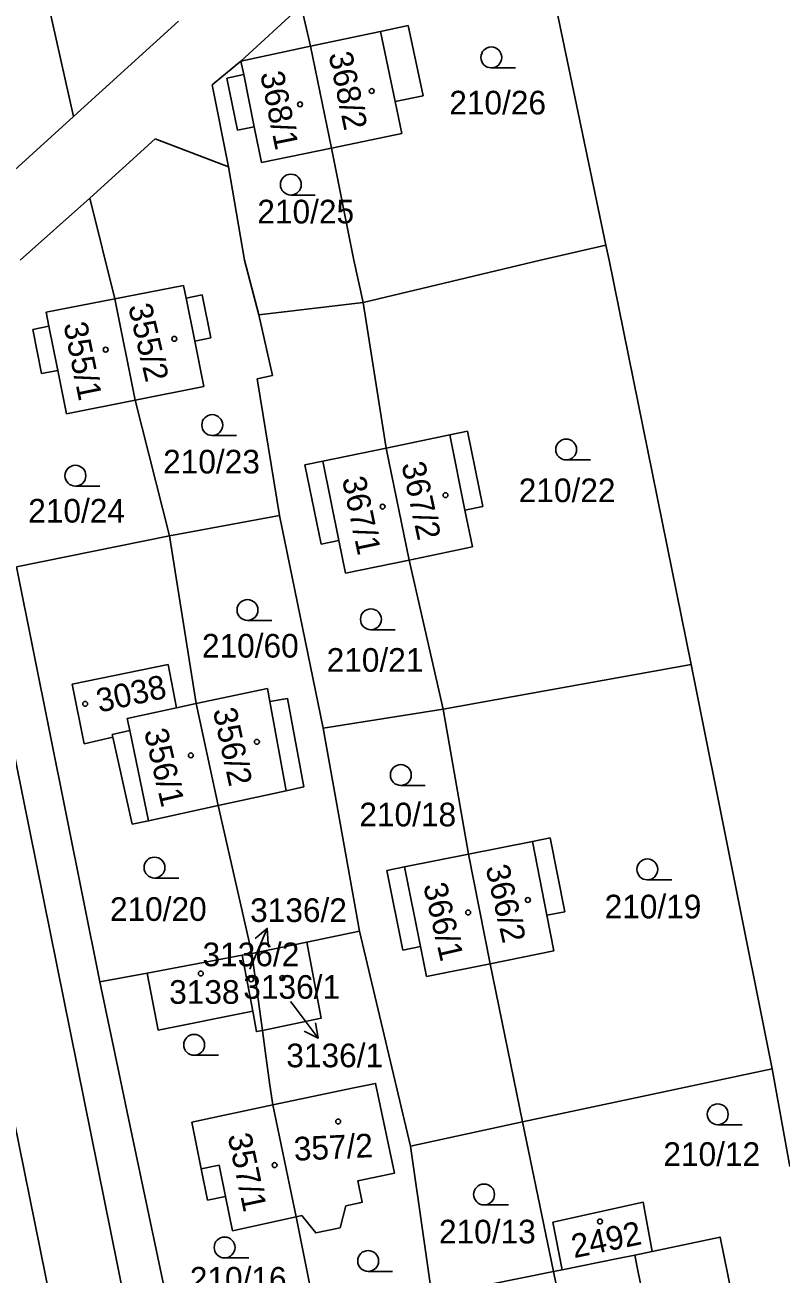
# Model space of a CAD drawing. Extents: x -735249 to -729401, y -1124843 to -1121828.
# Drawn here: x -733298.6 to -733244.3, y -1123572.8 to -1123483.1 of the extents above; entities that cross this region are included whole.
import ezdxf

# ---------------------------------------------------------------- set-up
doc = ezdxf.new("R2010")
doc.units = 0
for name, color, linetype in [('Vrstva 1', 7, 'Continuous'), ('Vrstva 16', 7, 'Continuous'), ('Vrstva 18', 7, 'Continuous'), ('Vrstva 19', 7, 'Continuous'), ('Vrstva 25', 7, 'Continuous'), ('Vrstva 4', 7, 'Continuous')]:
    doc.layers.add(name, color=color, linetype=linetype)

msp = doc.modelspace()

# ---------------------------------------------------------------- linework, layer by layer
at = {"layer": 'Vrstva 1'}
for points in [[(-733256.9, -1123498.91), (-733261.01, -1123479.3)], [(-733297.03, -1123481.32), (-733295.16, -1123489.66)], [(-733278.81, -1123481.71), (-733283.13, -1123485.69)], [(-733278.81, -1123481.71), (-733278.12, -1123484.62)], [(-733295.16, -1123489.66), (-733287.62, -1123482.81)], [(-733273.11, -1123483.55), (-733278.12, -1123484.62)], [(-733273.11, -1123483.55), (-733271.11, -1123483.12)], [(-733270.04, -1123488.18), (-733271.11, -1123483.12)], [(-733278.12, -1123484.62), (-733276.61, -1123491.94)], [(-733283.13, -1123485.69), (-733285.19, -1123487.38)], [(-733283.13, -1123485.69), (-733282.93, -1123486.66)], [(-733285.19, -1123487.38), (-733284.01, -1123493.28)], [(-733284.14, -1123486.91), (-733282.93, -1123486.66)], [(-733283.38, -1123490.65), (-733284.14, -1123486.91)], [(-733272.05, -1123488.6), (-733270.04, -1123488.18)], [(-733271.56, -1123490.9), (-733272.05, -1123488.6)], [(-733303.9, -1123497.59), (-733295.16, -1123489.66)], [(-733282.17, -1123490.41), (-733283.38, -1123490.65)], [(-733281.65, -1123492.98), (-733282.17, -1123490.41)], [(-733271.56, -1123490.9), (-733276.61, -1123491.94)], [(-733289.29, -1123491.28), (-733293.99, -1123495.53)], [(-733284.01, -1123493.28), (-733289.29, -1123491.28)], [(-733281.65, -1123492.98), (-733276.61, -1123491.94)], [(-733275.01, -1123500), (-733276.61, -1123491.94)], [(-733284.01, -1123493.28), (-733282.87, -1123500)], [(-733293.99, -1123495.53), (-733298.99, -1123500)], [(-733293.99, -1123495.53), (-733292.19, -1123502.77)], [(-733261.61, -1123500), (-733256.9, -1123498.91)], [(-733256.68, -1123500), (-733256.9, -1123498.91)], [(-733311.97, -1123500), (-733277.47, -1123670.28)], [(-733277.33, -1123644.79), (-733306.61, -1123500)], [(-733282.87, -1123500), (-733281.83, -1123503.91)], [(-733274.35, -1123503.04), (-733275.01, -1123500)], [(-733274.35, -1123503.04), (-733261.61, -1123500)], [(-733250.77, -1123529.05), (-733256.68, -1123500)], [(-733292.19, -1123502.77), (-733287.25, -1123501.81)], [(-733287.25, -1123501.81), (-733287.07, -1123502.72)], [(-733285.91, -1123502.49), (-733287.07, -1123502.72)], [(-733285.3, -1123505.58), (-733285.91, -1123502.49)], [(-733292.19, -1123502.77), (-733297.12, -1123503.72)], [(-733290.73, -1123510.06), (-733292.19, -1123502.77)], [(-733281.83, -1123503.91), (-733274.35, -1123503.04)], [(-733272.7, -1123513.5), (-733274.35, -1123503.04)], [(-733297.12, -1123503.72), (-733296.92, -1123504.74)], [(-733281.83, -1123503.91), (-733280.85, -1123508.27)], [(-733296.92, -1123504.74), (-733298.08, -1123504.97)], [(-733298.08, -1123504.97), (-733297.45, -1123508.14)], [(-733286.45, -1123505.81), (-733285.3, -1123505.58)], [(-733285.8, -1123509.08), (-733286.45, -1123505.81)], [(-733297.45, -1123508.14), (-733296.28, -1123507.91)], [(-733296.28, -1123507.91), (-733295.66, -1123511.04)], [(-733280.85, -1123508.27), (-733281.97, -1123508.51)], [(-733281.97, -1123508.51), (-733280.35, -1123518.33)], [(-733285.8, -1123509.08), (-733290.73, -1123510.06)], [(-733295.66, -1123511.04), (-733290.73, -1123510.06)], [(-733290.73, -1123510.06), (-733288.27, -1123519.79)], [(-733268.11, -1123512.55), (-733272.7, -1123513.5)], [(-733266.85, -1123512.29), (-733268.11, -1123512.55)], [(-733265.75, -1123517.7), (-733266.85, -1123512.29)], [(-733277.24, -1123514.43), (-733272.7, -1123513.5)], [(-733272.7, -1123513.5), (-733271.05, -1123521.54)], [(-733278.54, -1123514.7), (-733277.24, -1123514.43)], [(-733278.54, -1123514.7), (-733277.36, -1123520.4)], [(-733267.03, -1123517.96), (-733265.75, -1123517.7)], [(-733266.49, -1123520.6), (-733267.03, -1123517.96)], [(-733288.27, -1123519.79), (-733280.35, -1123518.33)], [(-733280.35, -1123518.33), (-733277.22, -1123533.61)], [(-733299.25, -1123522.02), (-733288.27, -1123519.79)], [(-733286.34, -1123531.86), (-733288.27, -1123519.79)], [(-733277.36, -1123520.4), (-733276.09, -1123520.13)], [(-733276.09, -1123520.13), (-733275.61, -1123522.48)], [(-733271.05, -1123521.54), (-733266.49, -1123520.6)], [(-733275.61, -1123522.48), (-733271.05, -1123521.54)], [(-733271.05, -1123521.54), (-733268.59, -1123532.26)], [(-733299.25, -1123522.02), (-733293.27, -1123551.85)], [(-733288.35, -1123529.05), (-733295.26, -1123530.46)], [(-733288.35, -1123529.05), (-733287.76, -1123532.16)], [(-733268.59, -1123532.26), (-733250.77, -1123529.05)], [(-733244.97, -1123558.11), (-733250.77, -1123529.05)], [(-733295.26, -1123530.46), (-733294.4, -1123534.74)], [(-733281.23, -1123530.77), (-733286.34, -1123531.86)], [(-733281.23, -1123530.77), (-733281.05, -1123531.71)], [(-733291.31, -1123532.92), (-733287.76, -1123532.16)], [(-733286.34, -1123531.86), (-733287.76, -1123532.16)], [(-733284.76, -1123539.18), (-733286.34, -1123531.86)], [(-733279.78, -1123531.48), (-733281.05, -1123531.71)], [(-733278.6, -1123537.84), (-733279.78, -1123531.48)], [(-733277.22, -1123533.61), (-733268.59, -1123532.26)], [(-733268.59, -1123532.26), (-733266.78, -1123542.68)], [(-733291.31, -1123532.92), (-733291.11, -1123533.8)], [(-733292.38, -1123534.08), (-733291.11, -1123533.8)], [(-733292.38, -1123534.08), (-733292.34, -1123534.28)], [(-733274.6, -1123548.2), (-733277.22, -1123533.61)], [(-733292.34, -1123534.28), (-733294.4, -1123534.74)], [(-733290.94, -1123540.53), (-733292.34, -1123534.28)], [(-733284.76, -1123539.18), (-733279.87, -1123538.12)], [(-733278.6, -1123537.84), (-733279.87, -1123538.12)], [(-733289.76, -1123540.27), (-733284.76, -1123539.18)], [(-733284.76, -1123539.18), (-733282.34, -1123549.81)], [(-733290.94, -1123540.53), (-733289.76, -1123540.27)], [(-733266.78, -1123542.68), (-733262.18, -1123541.77)], [(-733260.9, -1123541.51), (-733262.18, -1123541.77)], [(-733260.9, -1123541.51), (-733259.86, -1123546.81)], [(-733271.37, -1123543.59), (-733266.78, -1123542.68)], [(-733266.78, -1123542.68), (-733265.22, -1123550.55)], [(-733272.65, -1123543.85), (-733271.37, -1123543.59)], [(-733272.65, -1123543.85), (-733271.5, -1123549.57)], [(-733259.86, -1123546.81), (-733261.14, -1123547.06)], [(-733260.64, -1123549.63), (-733261.14, -1123547.06)], [(-733274.6, -1123548.2), (-733278.4, -1123548.99)], [(-733274.6, -1123548.2), (-733270.95, -1123563.66)], [(-733278.4, -1123548.99), (-733282.34, -1123549.81)], [(-733278.4, -1123548.99), (-733277.37, -1123554.47), (-733281.58, -1123555.34)], [(-733271.5, -1123549.57), (-733270.22, -1123549.31)], [(-733269.79, -1123551.46), (-733270.22, -1123549.31)], [(-733283.03, -1123549.94), (-733289.87, -1123551.22)], [(-733282.34, -1123549.81), (-733283.03, -1123549.94)], [(-733282.28, -1123553.95), (-733283.03, -1123549.94)], [(-733282.34, -1123549.81), (-733281.58, -1123555.34)], [(-733265.22, -1123550.55), (-733260.64, -1123549.63)], [(-733269.79, -1123551.46), (-733265.22, -1123550.55)], [(-733262.9, -1123561.91), (-733265.22, -1123550.55)], [(-733289.87, -1123551.22), (-733293.27, -1123551.85)], [(-733293.27, -1123551.85), (-733291.78, -1123558.91), (-733291.29, -1123561.22), (-733287.18, -1123580.75)], [(-733289.87, -1123551.22), (-733289.07, -1123555.32)], [(-733289.07, -1123555.32), (-733282.28, -1123553.95)], [(-733281.58, -1123555.34), (-733282.01, -1123555.43), (-733282.28, -1123553.95)], [(-733281.58, -1123555.34), (-733281.38, -1123556.8), (-733281.04, -1123559.28), (-733280.84, -1123560.7)], [(-733262.9, -1123561.91), (-733244.97, -1123558.11)], [(-733244.97, -1123558.11), (-733243.68, -1123565.12)], [(-733275.02, -1123559.47), (-733273.45, -1123559.15), (-733272.09, -1123565.6), (-733274.74, -1123566.16), (-733274.42, -1123567.69), (-733274.58, -1123567.73)], [(-733275.02, -1123559.47), (-733280.84, -1123560.7)], [(-733286.66, -1123561.93), (-733280.84, -1123560.7)], [(-733280.84, -1123560.7), (-733279.16, -1123568.74)], [(-733286.66, -1123561.93), (-733285.99, -1123565.28)], [(-733270.95, -1123563.66), (-733262.9, -1123561.91)], [(-733260.68, -1123572.67), (-733262.9, -1123561.91)], [(-733269.02, -1123577.02), (-733270.95, -1123563.66)], [(-733285.99, -1123565.28), (-733285.54, -1123567.54)], [(-733285.54, -1123567.54), (-733284.23, -1123567.28)], [(-733283.74, -1123569.74), (-733284.23, -1123567.28)], [(-733275.59, -1123567.95), (-733276, -1123569.52), (-733277.75, -1123569.89), (-733278.75, -1123568.65)], [(-733274.58, -1123567.73), (-733275.59, -1123567.95)], [(-733260.73, -1123569.13), (-733254.24, -1123567.69)], [(-733253.58, -1123571.23), (-733254.24, -1123567.69)], [(-733283.74, -1123569.74), (-733279.16, -1123568.74)], [(-733278.75, -1123568.65), (-733279.16, -1123568.74)], [(-733277.12, -1123578.95), (-733279.16, -1123568.74)], [(-733260.05, -1123572.54), (-733260.73, -1123569.13)], [(-733253.58, -1123571.23), (-733248.7, -1123570.19), (-733247.1, -1123578.09), (-733254.45, -1123579.57)], [(-733256.05, -1123571.74), (-733260.05, -1123572.54)], [(-733254.83, -1123571.49), (-733256.05, -1123571.74)], [(-733254.83, -1123571.49), (-733253.58, -1123571.23)], [(-733254.83, -1123571.49), (-733254.63, -1123572.48)], [(-733260.68, -1123572.67), (-733265.29, -1123573.6)], [(-733260.05, -1123572.54), (-733260.68, -1123572.67)], [(-733259.07, -1123580.5), (-733260.68, -1123572.67)], [(-733254.63, -1123572.48), (-733253.77, -1123576.66)]]:
    msp.add_lwpolyline(points, dxfattribs=at)
at = {"layer": 'Vrstva 16'}
for points in [[(-733282.49, -1123550.93), (-733282.42, -1123550.77)], [(-733279.56, -1123553.27), (-733279.38, -1123553.5)]]:
    msp.add_lwpolyline(points, dxfattribs=at)
at = {"layer": 'Vrstva 25'}
for points in [[(-733265.14, -1123486.17), (-733263.39, -1123486.17)], [(-733279.54, -1123495.31), (-733277.79, -1123495.31)], [(-733285.19, -1123512.59), (-733283.44, -1123512.59)], [(-733259.76, -1123514.35), (-733258.01, -1123514.35)], [(-733295.02, -1123516.23), (-733293.27, -1123516.23)], [(-733282.66, -1123525.88), (-733280.91, -1123525.88)], [(-733273.79, -1123526.55), (-733272.04, -1123526.55)], [(-733271.64, -1123537.74), (-733269.89, -1123537.74)], [(-733289.34, -1123544.39), (-733287.59, -1123544.39)], [(-733253.93, -1123544.52), (-733252.18, -1123544.52)], [(-733282.42, -1123550.77), (-733281.243, -1123548.011)], [(-733282.096, -1123548.735), (-733281.243, -1123548.011), (-733281.176, -1123549.127)], [(-733279.38, -1123553.5), (-733277.571, -1123555.892)], [(-733277.775, -1123554.793), (-733277.571, -1123555.892), (-733278.573, -1123555.396)], [(-733286.49, -1123557.13), (-733284.74, -1123557.13)], [(-733248.87, -1123562.12), (-733247.12, -1123562.12)], [(-733248.87, -1123562.12), (-733247.12, -1123562.12)], [(-733265.66, -1123567.88), (-733263.91, -1123567.88)], [(-733284.3, -1123571.69), (-733282.55, -1123571.69)], [(-733273.99, -1123572.66), (-733272.24, -1123572.66)]]:
    msp.add_lwpolyline(points, dxfattribs=at)
for centre, radius in [((-733265.14, -1123485.42), 0.75), ((-733273.73, -1123487.84), 0.175), ((-733278.88, -1123488.79), 0.175), ((-733279.54, -1123494.56), 0.75), ((-733292.85, -1123506.42), 0.175), ((-733287.91, -1123505.64), 0.175), ((-733285.19, -1123511.84), 0.75), ((-733259.76, -1123513.6), 0.75), ((-733295.02, -1123515.48), 0.75), ((-733268.43, -1123516.88), 0.175), ((-733272.95, -1123517.7), 0.175), ((-733282.66, -1123525.13), 0.75), ((-733273.79, -1123525.8), 0.75), ((-733294.32, -1123531.87), 0.175), ((-733281.98, -1123534.6), 0.175), ((-733286.73, -1123535.58), 0.175), ((-733271.64, -1123536.99), 0.75), ((-733289.34, -1123543.64), 0.75), ((-733253.93, -1123543.77), 0.75), ((-733262.51, -1123545.97), 0.175), ((-733266.8, -1123546.87), 0.175), ((-733286.01, -1123551.25), 0.175), ((-733282.39, -1123551.67), 0.175), ((-733280.15, -1123551.58), 0.175), ((-733286.49, -1123556.38), 0.75), ((-733248.87, -1123561.37), 0.75), ((-733248.87, -1123561.37), 0.75), ((-733276.14, -1123561.89), 0.175), ((-733280.71, -1123565.02), 0.175), ((-733265.66, -1123567.13), 0.75), ((-733257.33, -1123569.07), 0.175), ((-733284.3, -1123570.94), 0.75), ((-733273.99, -1123571.91), 0.75)]:
    msp.add_circle(centre, radius, dxfattribs=at)
at = {"layer": 'Vrstva 4'}
for points in [[(-733273.11, -1123483.55), (-733272.05, -1123488.6)], [(-733283.13, -1123485.69), (-733278.12, -1123484.62)], [(-733282.93, -1123486.66), (-733282.17, -1123490.41)], [(-733287.07, -1123502.72), (-733286.45, -1123505.81)], [(-733296.92, -1123504.74), (-733296.28, -1123507.91)], [(-733268.11, -1123512.55), (-733267.03, -1123517.96)], [(-733277.24, -1123514.43), (-733276.09, -1123520.13)], [(-733279.87, -1123538.12), (-733281.05, -1123531.71)], [(-733289.76, -1123540.27), (-733291.11, -1123533.8)], [(-733262.18, -1123541.77), (-733261.14, -1123547.06)], [(-733271.37, -1123543.59), (-733270.22, -1123549.31)], [(-733285.99, -1123565.28), (-733284.69, -1123565.02)], [(-733284.69, -1123565.02), (-733284.23, -1123567.28)]]:
    msp.add_lwpolyline(points, dxfattribs=at)

# ---------------------------------------------------------------- texts
at = {"layer": 'Vrstva 16'}
for s, p in [('3136/2', (-733282.468, -1123547.55)), ('3136/1', (-733279.868, -1123557.99))]:
    msp.add_text(s, height=1.7, dxfattribs=at).set_placement(p)
at = {"layer": 'Vrstva 18'}
for s, p in [('210/26', (-733268.16, -1123489.52)), ('210/25', (-733281.95, -1123497.35)), ('210/23', (-733288.72, -1123515.32)), ('210/22', (-733263.17, -1123517.38)), ('210/24', (-733298.41, -1123518.85)), ('210/60', (-733285.93, -1123528.55)), ('210/21', (-733276.97, -1123529.57)), ('210/18', (-733274.62, -1123540.68)), ('210/20', (-733292.54, -1123547.47)), ('210/19', (-733257, -1123547.29)), ('210/12', (-733252.778, -1123565.08)), ('210/13', (-733268.9, -1123570.65)), ('210/16', (-733286.8, -1123574.04))]:
    msp.add_text(s, height=1.7, dxfattribs=at).set_placement(p)
at = {"layer": 'Vrstva 19'}
for s, rotation, p in [('368/2', 281.80224, (-733276.844, -1123485.184)), ('368/1', 281.40224, (-733281.755, -1123486.576)), ('355/2', 283.20225, (-733291.24, -1123503.309)), ('355/1', 281.50224, (-733295.885, -1123504.596)), ('367/2', 282.20224, (-733271.603, -1123514.653)), ('367/1', 281.80224, (-733275.874, -1123515.704)), ('3038', 12.5001, (-733293.309, -1123532.512)), ('356/2', 282.20224, (-733285.153, -1123532.333)), ('356/1', 283.10225, (-733290.1, -1123533.839)), ('366/2', 282.90225, (-733265.561, -1123543.62)), ('366/1', 283.00225, (-733270.041, -1123544.919)), ('357/1', 282.00224, (-733284.093, -1123562.904)), ('357/2', 2.70002, (-733279.29, -1123564.711)), ('2492', 11.70009, (-733259.195, -1123571.714))]:
    msp.add_text(s, height=1.7, rotation=rotation, dxfattribs=at).set_placement(p)
for s, p in [('3136/2', (-733285.888, -1123550.73)), ('3138', (-733288.283, -1123553.43)), ('3136/1', (-733282.958, -1123553.07))]:
    msp.add_text(s, height=1.7, dxfattribs=at).set_placement(p)

doc.saveas('drawing.dxf')
